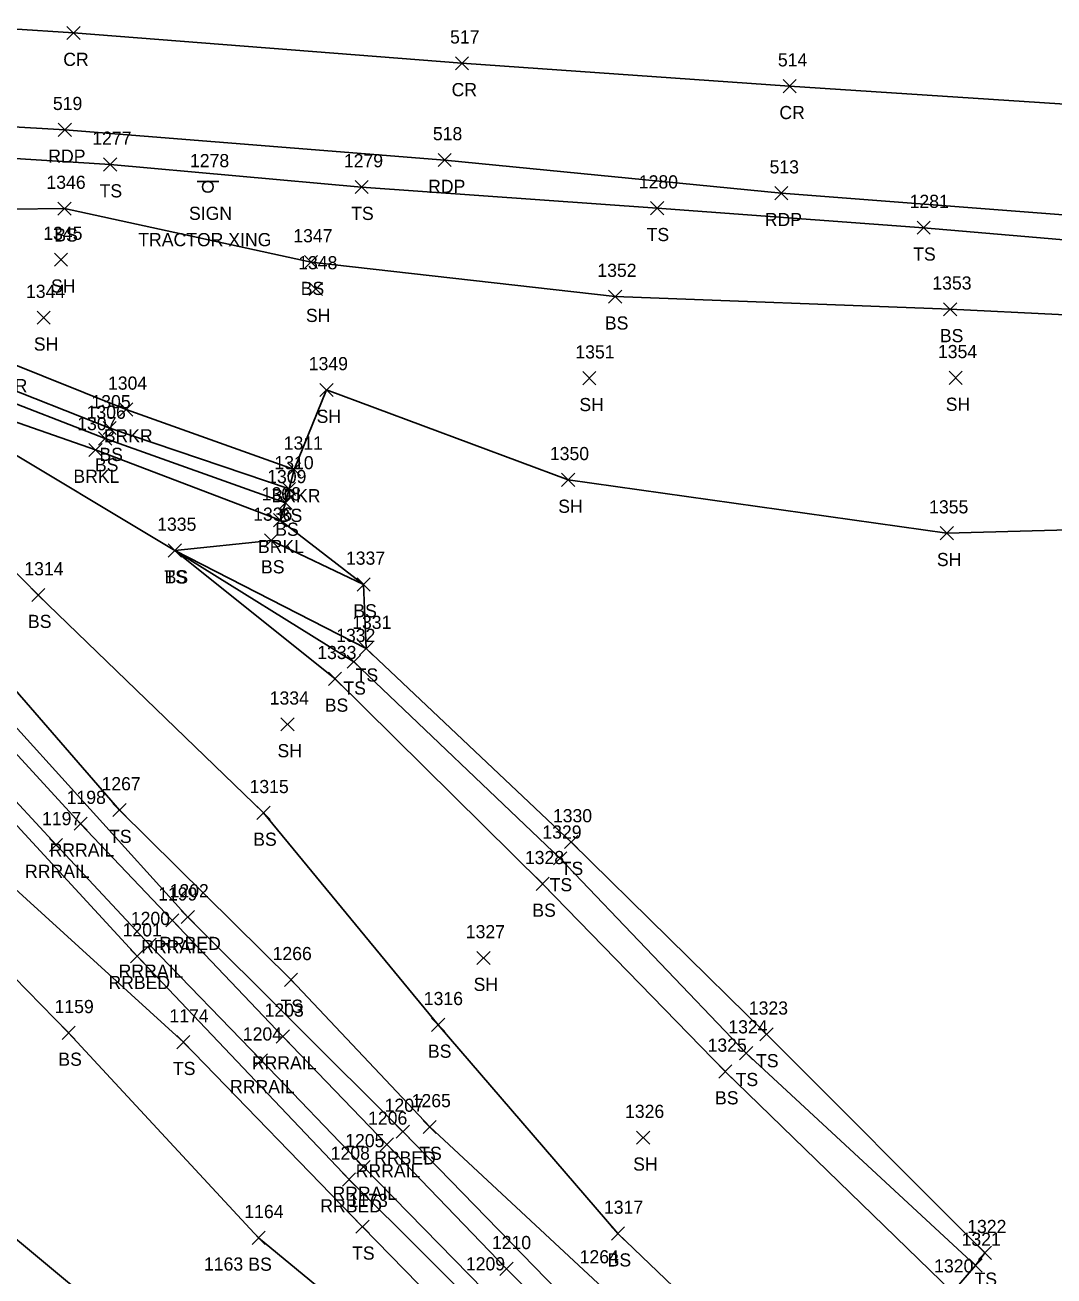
# Model space of a CAD drawing. Extents: x 1679360 to 1685861, y 903420 to 905946.
# Drawn here: x 1679933.1 to 1680089.3, y 903832.2 to 904022.2 of the extents above; entities that cross this region are included whole.
import ezdxf

# ---------------------------------------------------------------- set-up
doc = ezdxf.new("R2010")
doc.units = 0
for name, color, linetype in [('L_A', 7, 'Continuous'), ('L_I', 7, 'Continuous'), ('L_TIC', 7, 'Continuous'), ('LAWE', 7, 'Continuous'), ('LELB', 7, 'Continuous'), ('LSOGP', 7, 'Continuous'), ('P_A', 7, 'Continuous'), ('P_I', 7, 'Continuous'), ('P_TIC', 7, 'Continuous'), ('PET', 7, 'Continuous'), ('PRC', 7, 'Continuous'), ('R_A', 7, 'Continuous'), ('R_I', 7, 'Continuous'), ('R_TIC', 7, 'Continuous'), ('RR', 7, 'Continuous'), ('RRB', 7, 'Continuous'), ('S_A', 7, 'Continuous'), ('S_C', 7, 'Continuous'), ('S_I', 7, 'Continuous'), ('SSGN', 7, 'Continuous')]:
    doc.layers.add(name, color=color, linetype=linetype)

msp = doc.modelspace()

# ---------------------------------------------------------------- linework, layer by layer
at = {"layer": 'L_TIC'}
for points in [[(1679945.05, 904000.02), (1679947.05, 904002.02)], [(1679947.05, 904000.02), (1679945.05, 904002.02)], [(1679983.24, 903996.59), (1679985.24, 903998.59)], [(1679985.24, 903996.59), (1679983.24, 903998.59)], [(1679938.14, 903993.32), (1679940.14, 903995.32)], [(1679940.14, 903993.32), (1679938.14, 903995.32)], [(1680028.09, 903993.38), (1680030.09, 903995.38)], [(1680030.09, 903993.38), (1680028.09, 903995.38)], [(1680068.55, 903990.42), (1680070.55, 903992.42)], [(1680070.55, 903990.42), (1680068.55, 903992.42)], [(1679937.6, 903985.57), (1679939.6, 903987.57)], [(1679939.6, 903985.57), (1679937.6, 903987.57)], [(1679975.55, 903985.2), (1679977.55, 903987.2)], [(1679977.55, 903985.2), (1679975.55, 903987.2)], [(1679976.29, 903981.1), (1679978.29, 903983.1)], [(1679978.29, 903981.1), (1679976.29, 903983.1)], [(1680021.71, 903979.95), (1680023.71, 903981.95)], [(1680023.71, 903979.95), (1680021.71, 903981.95)], [(1680072.57, 903978.03), (1680074.57, 903980.03)], [(1680074.57, 903978.03), (1680072.57, 903980.03)], [(1679934.98, 903976.75), (1679936.98, 903978.75)], [(1679936.98, 903976.75), (1679934.98, 903978.75)], [(1680017.81, 903967.56), (1680019.81, 903969.56)], [(1680019.81, 903967.56), (1680017.81, 903969.56)], [(1680073.41, 903967.61), (1680075.41, 903969.61)], [(1680075.41, 903967.61), (1680073.41, 903969.61)], [(1679977.91, 903965.78), (1679979.91, 903967.78)], [(1679979.91, 903965.78), (1679977.91, 903967.78)], [(1679947.5, 903962.82), (1679949.5, 903964.82)], [(1679949.5, 903962.82), (1679947.5, 903964.82)], [(1679944.99, 903960), (1679946.99, 903962)], [(1679946.99, 903960), (1679944.99, 903962)], [(1679944.31, 903958.4), (1679946.31, 903960.4)], [(1679946.31, 903958.4), (1679944.31, 903960.4)], [(1679942.84, 903956.67), (1679944.84, 903958.67)], [(1679944.84, 903956.67), (1679942.84, 903958.67)], [(1679972.97, 903953.72), (1679974.97, 903955.72)], [(1679974.97, 903953.72), (1679972.97, 903955.72)], [(1679972.22, 903950.74), (1679974.22, 903952.74)], [(1679974.22, 903950.74), (1679972.22, 903952.74)], [(1680014.59, 903952.12), (1680016.59, 903954.12)], [(1680016.59, 903952.12), (1680014.59, 903954.12)], [(1679971.68, 903948.63), (1679973.68, 903950.63)], [(1679973.68, 903948.63), (1679971.68, 903950.63)], [(1679970.85, 903946.01), (1679972.85, 903948.01)], [(1679972.85, 903946.01), (1679970.85, 903948.01)], [(1679969.51, 903942.92), (1679971.51, 903944.92)], [(1679971.51, 903942.92), (1679969.51, 903944.92)], [(1680072.07, 903944.03), (1680074.07, 903946.03)], [(1680074.07, 903944.03), (1680072.07, 903946.03)], [(1679954.89, 903941.39), (1679956.89, 903943.39)], [(1679956.89, 903941.39), (1679954.89, 903943.39)], [(1679954.89, 903941.39), (1679956.89, 903943.39)], [(1679956.89, 903941.39), (1679954.89, 903943.39)], [(1679954.89, 903941.39), (1679956.89, 903943.39)], [(1679956.89, 903941.39), (1679954.89, 903943.39)], [(1679983.54, 903936.24), (1679985.54, 903938.24)], [(1679985.54, 903936.24), (1679983.54, 903938.24)], [(1679934.15, 903934.63), (1679936.15, 903936.63)], [(1679936.15, 903934.63), (1679934.15, 903936.63)], [(1679983.92, 903926.49), (1679985.92, 903928.49)], [(1679985.92, 903926.49), (1679983.92, 903928.49)], [(1679982.06, 903924.51), (1679984.06, 903926.51)], [(1679984.06, 903924.51), (1679982.06, 903926.51)], [(1679979.2, 903921.91), (1679981.2, 903923.91)], [(1679981.2, 903921.91), (1679979.2, 903923.91)], [(1679971.97, 903915), (1679973.97, 903917)], [(1679973.97, 903915), (1679971.97, 903917)], [(1679946.49, 903901.98), (1679948.49, 903903.98)], [(1679948.49, 903901.98), (1679946.49, 903903.98)], [(1679968.34, 903901.55), (1679970.34, 903903.55)], [(1679970.34, 903901.55), (1679968.34, 903903.55)], [(1680015.05, 903897.12), (1680017.05, 903899.12)], [(1680017.05, 903897.12), (1680015.05, 903899.12)], [(1680013.37, 903894.64), (1680015.37, 903896.64)], [(1680015.37, 903894.64), (1680013.37, 903896.64)], [(1680010.71, 903890.77), (1680012.71, 903892.77)], [(1680012.71, 903890.77), (1680010.71, 903892.77)], [(1680001.74, 903879.51), (1680003.74, 903881.51)], [(1680003.74, 903879.51), (1680001.74, 903881.51)], [(1679972.52, 903876.19), (1679974.52, 903878.19)], [(1679974.52, 903876.19), (1679972.52, 903878.19)], [(1679994.86, 903869.36), (1679996.86, 903871.36)], [(1679996.86, 903869.36), (1679994.86, 903871.36)], [(1679938.76, 903868.14), (1679940.76, 903870.14)], [(1679940.76, 903868.14), (1679938.76, 903870.14)], [(1680044.7, 903867.92), (1680046.7, 903869.92)], [(1680046.7, 903867.92), (1680044.7, 903869.92)], [(1679956.18, 903866.74), (1679958.18, 903868.74)], [(1679958.18, 903866.74), (1679956.18, 903868.74)], [(1680041.6, 903865.06), (1680043.6, 903867.06)], [(1680043.6, 903865.06), (1680041.6, 903867.06)], [(1680038.44, 903862.28), (1680040.44, 903864.28)], [(1680040.44, 903862.28), (1680038.44, 903864.28)], [(1679993.57, 903853.85), (1679995.57, 903855.85)], [(1679995.57, 903853.85), (1679993.57, 903855.85)], [(1680025.97, 903852.22), (1680027.97, 903854.22)], [(1680027.97, 903852.22), (1680025.97, 903854.22)], [(1679983.38, 903838.7), (1679985.38, 903840.7)], [(1679985.38, 903838.7), (1679983.38, 903840.7)], [(1679967.6, 903837.01), (1679969.6, 903839.01)], [(1679969.6, 903837.01), (1679967.6, 903839.01)], [(1680022.14, 903837.66), (1680024.14, 903839.66)], [(1680024.14, 903837.66), (1680022.14, 903839.66)], [(1680077.86, 903834.74), (1680079.86, 903836.74)], [(1680079.86, 903834.74), (1680077.86, 903836.74)], [(1680076.44, 903832.8), (1680078.44, 903834.8)], [(1680078.44, 903832.8), (1680076.44, 903834.8)]]:
    msp.add_lwpolyline(points, dxfattribs=at)
at = {"layer": 'LAWE'}
for points in [[(1679871.81, 903994.91), (1679890.31, 903994.48), (1679904.67, 903985.72), (1679929.47, 903971.44), (1679948.5, 903963.82), (1679973.97, 903954.72)], [(1679877.86, 903987.38), (1679888.19, 903983.81), (1679901.39, 903977.61), (1679926.81, 903963.59), (1679943.84, 903957.67), (1679971.85, 903947.01)]]:
    msp.add_lwpolyline(points, dxfattribs=at)
at = {"layer": 'LELB'}
for points in [[(1679868.12, 903992.58), (1679867.45, 903997.95), (1679872.23, 904006.64), (1679908.32, 904003.39), (1679946.05, 904001.02), (1679984.24, 903997.59), (1680029.09, 903994.38), (1680069.55, 903991.42), (1680115.05, 903987.49), (1680162.58, 903984.34), (1680207.95, 903980.99)], [(1679885.27, 903999.1), (1679906.49, 903993.95), (1679939.14, 903994.32), (1679976.55, 903986.2), (1680022.71, 903980.95), (1680073.57, 903979.03), (1680122.89, 903976.61), (1680170.41, 903973.98), (1680212.6, 903970.94)], [(1679872.59, 903994.19), (1679871.89, 903994.88), (1679890.1, 903992.1), (1679903.01, 903981.55), (1679927.79, 903968.15), (1679945.99, 903961), (1679973.22, 903951.74)], [(1679877.32, 903988.23), (1679889.49, 903986.11), (1679902.1, 903979.85), (1679927.27, 903966.37), (1679945.31, 903959.4), (1679972.68, 903949.63)], [(1680042.48, 903807.68), (1680020.07, 903831.14), (1679994.57, 903854.85), (1679973.52, 903877.19), (1679947.49, 903902.98), (1679918.08, 903936.81), (1679895.51, 903960.77), (1679875.1, 903984.26)], [(1679894.89, 903975.93), (1679910.27, 903960.99), (1679935.15, 903935.63), (1679969.34, 903902.55), (1679995.86, 903870.36), (1680023.14, 903838.66), (1680052.1, 903810.88)], [(1680077.44, 903833.8), (1680042.6, 903866.06), (1680014.37, 903895.64), (1679983.06, 903925.51), (1679955.89, 903942.39), (1679926.81, 903959.82), (1679904.72, 903971.01)], [(1679854.83, 903964.92), (1679872.81, 903942.29), (1679891.12, 903918.82), (1679918.93, 903890.39), (1679939.76, 903869.14), (1679968.6, 903838.01), (1679992.84, 903818.01), (1680020.69, 903787.69)], [(1680027, 903796.8), (1680001.4, 903822.24), (1679984.38, 903839.7), (1679957.18, 903867.74), (1679928.2, 903894.12), (1679909.11, 903915.88), (1679887.98, 903941.49), (1679868.32, 903960.05)], [(1680073.91, 903829.75), (1680039.44, 903863.28), (1680011.71, 903891.77), (1679980.2, 903922.91), (1679955.89, 903942.39), (1679970.51, 903943.92), (1679984.54, 903937.24)], [(1680078.86, 903835.74), (1680045.7, 903868.92), (1680016.05, 903898.12), (1679984.92, 903927.49), (1679955.89, 903942.39)]]:
    msp.add_lwpolyline(points, dxfattribs=at)
at = {"layer": 'LSOGP'}
for points in [[(1680073.91, 903829.75), (1680077.44, 903833.8), (1680078.86, 903835.74), (1680045.7, 903868.92), (1680016.05, 903898.12), (1679984.92, 903927.49), (1679984.54, 903937.24), (1679971.85, 903947.01), (1679972.68, 903949.63), (1679973.22, 903951.74), (1679973.97, 903954.72), (1679978.91, 903966.78), (1680015.59, 903953.12), (1680073.07, 903945.03), (1680113.84, 903946.16)], [(1679809.97, 903931.78), (1679849.71, 903926.51), (1679875.37, 903898.2), (1679896.61, 903875.28), (1679920.81, 903846.9), (1679951.04, 903821.8)]]:
    msp.add_lwpolyline(points, dxfattribs=at)
at = {"layer": 'P_TIC'}
for points in [[(1679939.5, 904019.99), (1679941.5, 904021.99)], [(1679941.5, 904019.99), (1679939.5, 904021.99)], [(1679998.46, 904015.39), (1680000.46, 904017.39)], [(1680000.46, 904015.39), (1679998.46, 904017.39)], [(1680048.21, 904011.91), (1680050.21, 904013.91)], [(1680050.21, 904011.91), (1680048.21, 904013.91)], [(1679938.18, 904005.29), (1679940.18, 904007.29)], [(1679940.18, 904005.29), (1679938.18, 904007.29)], [(1679995.84, 904000.7), (1679997.84, 904002.7)], [(1679997.84, 904000.7), (1679995.84, 904002.7)], [(1680046.95, 903995.66), (1680048.95, 903997.66)], [(1680048.95, 903995.66), (1680046.95, 903997.66)]]:
    msp.add_lwpolyline(points, dxfattribs=at)
at = {"layer": 'PET'}
msp.add_lwpolyline([(1680207.92, 903985.13), (1680151.69, 903989.51), (1680097.96, 903992.81), (1680047.95, 903996.66), (1679996.84, 904001.7), (1679939.18, 904006.29), (1679891.59, 904009.09), (1679852.59, 904011.92), (1679848.66, 904011.26), (1679842.11, 904010.48), (1679836.31, 904011.49), (1679826.76, 904014.61), (1679807.93, 904016.05), (1679789.63, 904016.53)], dxfattribs=at)
at = {"layer": 'PRC'}
msp.add_lwpolyline([(1680209.65, 904002.04), (1680152.97, 904005.78), (1680100.29, 904009.57), (1680049.21, 904012.91), (1679999.46, 904016.39), (1679940.5, 904020.99), (1679893.64, 904024.04), (1679847.03, 904027.44), (1679827.53, 904028.69), (1679808.61, 904029.86), (1679757.07, 904033.5), (1679707.39, 904036.98), (1679666.22, 904040.39), (1679623.03, 904043.25), (1679581.59, 904046.25), (1679534.87, 904049.67), (1679494.87, 904052.55), (1679467.34, 904054.68)], dxfattribs=at)
at = {"layer": 'R_TIC'}
for points in [[(1679940.58, 903899.91), (1679942.58, 903901.91)], [(1679942.58, 903899.91), (1679940.58, 903901.91)], [(1679936.85, 903896.68), (1679938.85, 903898.68)], [(1679938.85, 903896.68), (1679936.85, 903898.68)], [(1679954.49, 903885.24), (1679956.49, 903887.24)], [(1679956.49, 903885.24), (1679954.49, 903887.24)], [(1679956.86, 903885.73), (1679958.86, 903887.73)], [(1679958.86, 903885.73), (1679956.86, 903887.73)], [(1679951.05, 903881.52), (1679953.05, 903883.52)], [(1679953.05, 903881.52), (1679951.05, 903883.52)], [(1679949.15, 903879.79), (1679951.15, 903881.79)], [(1679951.15, 903879.79), (1679949.15, 903881.79)], [(1679971.28, 903867.6), (1679973.28, 903869.6)], [(1679973.28, 903867.6), (1679971.28, 903869.6)], [(1679967.97, 903863.98), (1679969.97, 903865.98)], [(1679969.97, 903863.98), (1679967.97, 903865.98)], [(1679989.5, 903853.15), (1679991.5, 903855.15)], [(1679991.5, 903853.15), (1679989.5, 903855.15)], [(1679987.05, 903851.2), (1679989.05, 903853.2)], [(1679989.05, 903851.2), (1679987.05, 903853.2)], [(1679983.51, 903847.78), (1679985.51, 903849.78)], [(1679985.51, 903847.78), (1679983.51, 903849.78)], [(1679981.32, 903845.88), (1679983.32, 903847.88)], [(1679983.32, 903845.88), (1679981.32, 903847.88)], [(1680005.22, 903832.3), (1680007.22, 903834.3)], [(1680007.22, 903832.3), (1680005.22, 903834.3)]]:
    msp.add_lwpolyline(points, dxfattribs=at)
at = {"layer": 'RR'}
for points in [[(1679824.64, 904028.72), (1679837.34, 904012.39), (1679861.93, 903982.57), (1679878.2, 903963.7), (1679892.43, 903947.81), (1679907.95, 903930.19), (1679922.38, 903914.41), (1679937.85, 903897.68), (1679952.05, 903882.52), (1679968.97, 903864.98), (1679984.51, 903848.78), (1680002.83, 903830.07), (1680018.62, 903814.03), (1680033.05, 903799.46), (1680047.5, 903784.67), (1680062.83, 903769.48), (1680079.58, 903752.46), (1680095.32, 903736.48)], [(1679831.29, 904028.45), (1679844.1, 904012.06), (1679865.83, 903985.59), (1679882.11, 903966.82), (1679896.05, 903950.91), (1679911.54, 903933.69), (1679925.87, 903917.93), (1679941.58, 903900.91), (1679955.49, 903886.24), (1679972.28, 903868.6), (1679988.05, 903852.2), (1680006.22, 903833.3), (1680022.22, 903817.37), (1680036.49, 903802.97), (1680051.11, 903788.21), (1680066.39, 903772.91), (1680082.82, 903756.11), (1680099.28, 903739.48)]]:
    msp.add_lwpolyline(points, dxfattribs=at)
at = {"layer": 'RRB'}
for points in [[(1679852.8, 904005.56), (1679867.15, 903987.02), (1679898.43, 903952.3), (1679928.17, 903919.5), (1679957.86, 903886.73), (1679990.5, 903854.15), (1680024.93, 903818.74), (1680038.52, 903804.88)], [(1679840.74, 904004.22), (1679860.45, 903979.99), (1679889.94, 903946.25), (1679920.7, 903912.73), (1679950.15, 903880.79), (1679982.32, 903846.88), (1680017.14, 903812.2), (1680030.44, 903798.07)]]:
    msp.add_lwpolyline(points, dxfattribs=at)
at = {"layer": 'SSGN'}
for p, q in [((1679959.25, 903998.46), (1679962.58, 903998.46)), ((1679960.89, 903997.63), (1679960.89, 903997.63))]:
    msp.add_line(p, q, dxfattribs=at)
msp.add_circle((1679960.89, 903997.63), 0.833, dxfattribs=at)

# ---------------------------------------------------------------- texts
at = {"layer": 'L_A'}
for s, p in [('TS', (1679944.46, 903996.02)), ('TS', (1679982.65, 903992.59)), ('BS', (1679937.58, 903989.32)), ('TS', (1680027.5, 903989.38)), ('TS', (1680067.96, 903986.42)), ('SH', (1679937.09, 903981.57)), ('BS', (1679974.99, 903981.2)), ('SH', (1679975.78, 903977.1)), ('BS', (1680021.16, 903975.95)), ('BS', (1680072.01, 903974.03)), ('SH', (1679934.47, 903972.75)), ('BRKR', (1679926.06, 903966.44)), ('SH', (1680072.9, 903963.61)), ('SH', (1679977.4, 903961.78)), ('SH', (1680017.29, 903963.56)), ('BRKR', (1679945.09, 903958.82)), ('BS', (1679943.75, 903954.4)), ('BS', (1679944.43, 903956)), ('BRKL', (1679940.48, 903952.67)), ('BRKR', (1679970.56, 903949.72)), ('BS', (1679971.66, 903946.74)), ('SH', (1680014.08, 903948.12)), ('BS', (1679971.12, 903944.63)), ('BRKL', (1679968.5, 903942.01)), ('BS', (1679968.96, 903938.92)), ('SH', (1680071.56, 903940.03)), ('TS', (1679954.3, 903937.39)), ('TS', (1679954.3, 903937.39)), ('BS', (1679954.33, 903937.39)), ('BS', (1679982.98, 903932.24)), ('BS', (1679933.59, 903930.63)), ('TS', (1679983.33, 903922.49)), ('TS', (1679981.47, 903920.51)), ('BS', (1679978.64, 903917.91)), ('SH', (1679971.46, 903911)), ('TS', (1679945.9, 903897.98)), ('BS', (1679967.78, 903897.55)), ('TS', (1680014.46, 903893.12)), ('TS', (1680012.78, 903890.64)), ('BS', (1680010.15, 903886.77)), ('SH', (1680001.23, 903875.51)), ('TS', (1679971.93, 903872.19)), ('BS', (1679994.3, 903865.36)), ('BS', (1679938.2, 903864.14)), ('TS', (1680044.11, 903863.92)), ('TS', (1679955.59, 903862.74)), ('TS', (1680041.01, 903861.06)), ('BS', (1680037.88, 903858.28)), ('TS', (1679992.98, 903849.85)), ('SH', (1680025.45, 903848.22)), ('TS', (1679982.79, 903834.7)), ('BS', (1679967.04, 903833.01)), ('BS', (1680021.58, 903833.66)), ('TS', (1680077.27, 903830.74))]:
    msp.add_text(s, height=2, dxfattribs=at).set_placement(p)
at = {"layer": 'L_I'}
for s, p in [('1277', (1679943.35, 904004.02)), ('1279', (1679981.54, 904000.59)), ('1346', (1679936.39, 903997.32)), ('1280', (1680026.31, 903997.38)), ('1281', (1680067.42, 903994.42)), ('1345', (1679935.91, 903989.57)), ('1347', (1679973.86, 903989.2)), ('1348', (1679974.6, 903985.1)), ('1352', (1680020.02, 903983.95)), ('1344', (1679933.29, 903980.75)), ('1353', (1680070.87, 903982.03)), ('1351', (1680016.68, 903971.56)), ('1354', (1680071.72, 903971.61)), ('1349', (1679976.21, 903969.78)), ('1304', (1679945.73, 903966.82)), ('1305', (1679943.22, 903964)), ('1306', (1679942.48, 903962.4)), ('1307', (1679941.06, 903960.67)), ('1311', (1679972.41, 903957.72)), ('1350', (1680012.81, 903956.12)), ('1310', (1679971, 903954.74)), ('1309', (1679969.9, 903952.63)), ('1308', (1679969.08, 903950.01)), ('1336', (1679967.77, 903946.92)), ('1355', (1680070.38, 903948.03)), ('1335', (1679953.2, 903945.39)), ('1335', (1679953.2, 903945.39)), ('1335', (1679953.2, 903945.39)), ('1337', (1679981.85, 903940.24)), ('1314', (1679933.03, 903938.63)), ('1331', (1679982.8, 903930.49)), ('1332', (1679980.37, 903928.51)), ('1333', (1679977.5, 903925.91)), ('1334', (1679970.28, 903919)), ('1267', (1679944.75, 903905.98)), ('1315', (1679967.22, 903905.55)), ('1330', (1680013.27, 903901.12)), ('1329', (1680011.67, 903898.64)), ('1328', (1680009.02, 903894.77)), ('1327', (1680000.05, 903883.51)), ('1266', (1679970.72, 903880.19)), ('1316', (1679993.67, 903873.36)), ('1159', (1679937.62, 903872.14)), ('1174', (1679955.06, 903870.74)), ('1323', (1680043.01, 903871.92)), ('1324', (1680039.9, 903869.06)), ('1325', (1680036.75, 903866.28)), ('1265', (1679991.83, 903857.85)), ('1326', (1680024.22, 903856.22)), ('1173', (1679982.26, 903842.7)), ('1164', (1679966.43, 903841.01)), ('1317', (1680021.02, 903841.66)), ('1322', (1680076.16, 903838.74)), ('1321', (1680075.31, 903836.8)), ('1163', (1679960.3, 903833.04)), ('1264', (1680017.33, 903834.14)), ('1320', (1680071.14, 903832.75))]:
    msp.add_text(s, height=2, dxfattribs=at).set_placement(p)
at = {"layer": 'P_A'}
for s, p in [('CR', (1679938.94, 904015.99)), ('CR', (1679997.89, 904011.39)), ('CR', (1680047.65, 904007.91)), ('RDP', (1679936.67, 904001.29)), ('RDP', (1679994.33, 903996.7)), ('RDP', (1680045.44, 903991.66))]:
    msp.add_text(s, height=2, dxfattribs=at).set_placement(p)
at = {"layer": 'P_I'}
for s, p in [('517', (1679997.66, 904019.39)), ('514', (1680047.42, 904015.91)), ('519', (1679937.37, 904009.29)), ('518', (1679995.05, 904004.7)), ('513', (1680046.16, 903999.66))]:
    msp.add_text(s, height=2, dxfattribs=at).set_placement(p)
at = {"layer": 'R_A'}
for s, p in [('RRRAIL', (1679936.87, 903895.91)), ('RRRAIL', (1679933.14, 903892.68)), ('RRRAIL', (1679950.78, 903881.24)), ('RRBED', (1679953.5, 903881.73)), ('RRRAIL', (1679947.35, 903877.52)), ('RRBED', (1679945.8, 903875.79)), ('RRRAIL', (1679967.57, 903863.6)), ('RRRAIL', (1679964.26, 903859.98)), ('RRBED', (1679986.14, 903849.15)), ('RRRAIL', (1679983.34, 903847.2)), ('RRRAIL', (1679979.81, 903843.78)), ('RRBED', (1679977.96, 903841.88))]:
    msp.add_text(s, height=2, dxfattribs=at).set_placement(p)
at = {"layer": 'R_I'}
for s, p in [('1198', (1679939.46, 903903.91)), ('1197', (1679935.72, 903900.68)), ('1202', (1679955.08, 903889.73)), ('1199', (1679953.35, 903889.24)), ('1200', (1679949.2, 903885.52)), ('1201', (1679947.95, 903883.79)), ('1203', (1679969.5, 903871.6)), ('1204', (1679966.2, 903867.98)), ('1207', (1679987.73, 903857.15)), ('1206', (1679985.22, 903855.2)), ('1205', (1679981.74, 903851.78)), ('1208', (1679979.54, 903849.88)), ('1210', (1680004.01, 903836.3)), ('1209', (1680000.06, 903833.07))]:
    msp.add_text(s, height=2, dxfattribs=at).set_placement(p)
at = {"layer": 'S_A'}
msp.add_text('SIGN', height=2, dxfattribs=at).set_placement((1679958.03, 903992.61))
at = {"layer": 'S_C'}
msp.add_text('TRACTOR XING', height=2, dxfattribs=at).set_placement((1679950.33, 903988.61))
at = {"layer": 'S_I'}
msp.add_text('1278', height=2, dxfattribs=at).set_placement((1679958.18, 904000.61))

doc.saveas('drawing.dxf')
